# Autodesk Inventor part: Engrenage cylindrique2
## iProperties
Created: 2011-10
Part Number: Engrenage cylindrique2
Material: Laiton (jaune doux)
Document SubType Name: Modeling
Designer: Laur
Mass: 0.65097 g
Surface Area: 1.97897 cm^2
Volume: 0.076856 cm^3
Density: 8.47 g/cm^3
CustomPartVersion: 1
Author: Laur
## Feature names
1. Extrusion1
2. alésage [Extrusion]
